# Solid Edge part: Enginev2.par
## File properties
Author: m_hel
Template: iso metric part.par
Last saved by: m_hel
Revision: 22
Application: Solid Edge
Density: 7,750 g/cm^3
Accuracy: 0,990
Username: m_hel
Material: Stainless steel
Face Style: Steel
Fill Style: ANSI32(Steel)
Virtual Style: Stainless steel
Grouping: Metals\Steel
LibraryName: Materials
Coef. of Thermal Exp: 1.6e-05
Thermal Conductivity: 17.0
Specific Heat: 502.0
Modulus of Elasticity: 193053196000.0
Poisson's Ratio: 0.29
Yield Stress: 310264065.0
Ultimate Stress: 641212401.0
Elongation: 0.0
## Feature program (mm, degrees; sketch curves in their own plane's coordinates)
sketch for "unnamed Protrusion 1" plane through (0, 0, 0) normal (0, 0, 1) x-axis (1, 0, 0)
  line (-200, -300) -> (200, -300)
  line (200, -300) -> (200, 300)
  line (200, 300) -> (-200, 300)
  line (-200, 300) -> (-200, -300)
extrude "unnamed Protrusion 1" add finite 100 along +normal
sketch for "ExtrudedProtrusion_2" plane through (0, 0, 0) normal (0, 0, -1) x-axis (0, -1, 0)
  line (-130.9637, 125) -> (-130.9637, -125)
  line (-130.9637, -125) -> (269.0363, -125)
  line (269.0363, -125) -> (269.0363, 125)
  line (269.0363, 125) -> (-130.9637, 125)
extrude "ExtrudedProtrusion_2" add finite 700 along +normal
draft "Draft_1"  Angles1 = 7 deg
sketch for "ExtrudedProtrusion_3" plane through (0, -25.292, -700) normal (0, 0, -1) x-axis (0, -1, 0)
  line (157.7951, 39.0508) -> (-156.2557, 39.0508)
  line (-156.2557, 39.0508) -> (-156.2557, -39.0508)
  line (-156.2557, -39.0508) -> (157.7951, -39.0508)
  line (157.7951, -39.0508) -> (157.7951, 39.0508)
extrude "ExtrudedProtrusion_3" add finite 200 along +normal
sketch for "ExtrudedProtrusion_4" plane through (0, -183.0871, -1100) normal (0, -1, 0) x-axis (1, 0, 0)
  line (39.0508, 400) -> (-39.0508, 400)
  line (-39.0508, 200) -> (-39.0508, 400)
  line (39.0508, 200) -> (-39.0508, 200)
  line (39.0508, 200) -> (39.0508, 400)
extrude "ExtrudedProtrusion_4" add finite 200 along +normal
sketch for "ExtrudedProtrusion_5" plane through (0, -125.292, -900) normal (0, 0, -1) x-axis (0, -1, 0)
  line (-226.2557, -5) -> (-226.2557, 5)
  arc centre (-206.2557, 5) radius 20 from (-226.2557, 5) to (-206.2557, 25) cw
  line (-206.2557, 25) -> (-76.2557, 13.6265)
  line (-76.2557, 13.6265) -> (-76.2557, -13.6265)
  line (-206.2557, -25) -> (-76.2557, -13.6265)
  arc centre (-206.2557, -5) radius 20 from (-226.2557, -5) to (-206.2557, -25) ccw
  dimension (linear) = 76.2557
extrude "ExtrudedProtrusion_5" add finite 450 along +normal
sketch for "ExtrudedProtrusion_6" plane through (0, -49.0363, -1350) normal (0, -1, 0) x-axis (0, 0, 1)
  circle centre (150, 0) radius 60
extrude "ExtrudedProtrusion_6" add finite 105.677 along +normal  FiniteDepth2 = 202.4091 mm
sketch for "ExtrudedProtrusion_7" plane through (0, -154.7133, -1400) normal (0, -1, 0) x-axis (1, 0, 0)
  circle centre (0, 200) radius 15
extrude "ExtrudedProtrusion_7" add finite 80 along +normal
fillet "Round_1" radius 40
sketch for "ExtrudedCutout_1" plane through (0, -281.5477, -700) normal (0, 0, 1) x-axis (0, -1, 0)
  line (-98.4605, -39.0508) -> (101.5395, -14.4939)
  line (101.5395, -14.4939) -> (101.5395, 14.4939)
  line (101.5395, 14.4939) -> (-98.4605, 39.0508)
extrude "ExtrudedCutout_1" cut finite 841.935 along -normal
fillet "Round_2" radius 36
sketch for "ExtrudedProtrusion_8" plane through (0, 0, 100) normal (0, 0, 1) x-axis (0, -1, 0)
  line (-280, 180) -> (-280, -180)
  line (-280, -180) -> (280, -180)
  line (280, -180) -> (280, 180)
  line (280, 180) -> (-280, 180)
extrude "ExtrudedProtrusion_8" add finite 446.6549 along +normal
replace surface "unnamed ReplaceSurface 1"
fillet "Round_3" radius 50
fillet "Round_4" radius 50
fillet "Round_5" radius 32.5
fillet "Round_6" radius 14.625
sketch for "ExtrudedProtrusion_9" plane through (0, 0, 0) normal (0, -1, 0) x-axis (1, 0, 0)
  line (-75, -122.6381) -> (75, -122.6381)
  line (75, -122.6381) -> (75, -92.6381)
  line (75, -92.6381) -> (-75, -92.6381)
  line (-75, -92.6381) -> (-75, -122.6381)
extrude "ExtrudedProtrusion_9" add finite 200 along -normal
sketch for "ExtrudedProtrusion_10" plane through (0, 193.9697, -122.6381) normal (0, 0, -1) x-axis (0, 1, 0)
  circle centre (6.0303, 0) radius 50
extrude "ExtrudedProtrusion_10" add finite 30 along -normal
sketch for "ExtrudedProtrusion_11" plane through (0, 0, 0) normal (1, 0, 0) x-axis (0, 1, 0)
  line (130.9637, -50) -> (160.9637, -72.6381)
  line (160.9637, -72.6381) -> (160.9637, -92.6381)
  line (160.9637, -92.6381) -> (130.9637, -92.6381)
  line (130.9637, -92.6381) -> (130.9637, -50)
  dimension (linear) = 160.9637
extrude "ExtrudedProtrusion_11" add finite 30 symmetric
fillet "Round_7" radius 10
chamfer "Chamfer_1" setback 10
mirror "unnamed Mirror 1" of "ExtrudedProtrusion_11", "ExtrudedProtrusion_10", "Round_7", "ExtrudedProtrusion_9" about plane through (0, 190.4818, -152.6381) normal (0, 0, -1)
extrude "unnamed Protrusion 2" add finite 200
extrude "unnamed Protrusion 3" add finite 30
extrude "unnamed Protrusion 4" add finite 30 symmetric
fillet "unnamed Round 1"
sketch for "unnamed Cutout 1" plane through (0, 218.9697, -92.6381) normal (0, 0, 1) x-axis (-1, 0, 0)
  circle centre (0, 18.9697) radius 25
extrude "unnamed Cutout 1" cut through along -normal
rib "unnamed Rib 1"
chamfer "Chamfer_3" setback 5
lofted protrusion "LoftedProtrusion_1"  EndTangentMagnitude1 = 1
sketch for "ExtrudedCutout_4" plane through (133.75, 340, 66.25) normal (0, 1, 0) x-axis (-1, 0, 0)
  circle centre (0, 0) radius 25
extrude "ExtrudedCutout_4" cut finite 50 along -normal
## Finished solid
Body 1: sheet body, 1 face, 4 edges, 4 vertices.
  Faces by surface: spline 1
  Edges by curve: circle 2, spline 2
Body 2: solid body, 162 faces, 387 edges, 228 vertices.
  Faces by surface: plane 66, cylinder 58, blend 18, sphere 8, spline 5, cone 4, torus 3
  Edges by curve: line 194, circle 106, intersection 45, ellipse 38, spline 4
Bounding box of the edges (mm; curved faces can reach further): 723.467 x 775.717 x 1838.647, from (-361.7335, -417.9835, -1350) to (361.7335, 357.7337, 488.6472).
Cylindrical faces by radius (mm): R10 x16, R14.625 x2, R15 x1, R20 x4, R25 x3, R32.5 x14, R36 x6, R50 x10, R60 x1, R125.7616 x1
Conical faces (half-angle, radius in mm at the cone's reference point): 45 deg R26 x2, 45 deg R125.7616 x1, 45 deg R130.7616 x1
Toroidal faces (ring radius, tube radius in mm): R20 r40 x1, R40 r10 x2
Spherical faces by radius (mm): R32.5 x4, R50 x4
Planar faces by outward normal: +x 8, +y 17, +z 4, -x 8, -y 6, -z 7, oblique 16
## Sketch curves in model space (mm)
circle centre (133.75, 340, 66.25) radius 33.75
line (167.5, 300, 32.5) -> (167.5, 300, 100)
line (167.5, 300, 100) -> (100, 300, 100)
line (100, 300, 100) -> (100, 300, 32.5)
line (100, 300, 32.5) -> (167.5, 300, 32.5)
arc centre (0, 0, -166.6274) radius 655.2478 from (0, 0, 488.6204) through (188.8848, 0, 460.8056) to (361.7335, 0, 379.7228)
arc centre (0, 0, -166.6274) radius 655.2478 from (0, 0, 488.6204) through (-188.8848, 0, 460.8056) to (-361.7335, 0, 379.7228)
spline (0, 357.7337, 404.8039) -> (0, 3.7266, 488.327) -> (0, -417.9835, 466.9366)
line (-180, -280, 100) -> (180, -280, 100)
line (180, -280, 100) -> (180, 280, 100)
line (180, 280, 100) -> (-180, 280, 100)
line (-180, 280, 100) -> (-180, -280, 100)
line (125, -269.0363, 0) -> (-125, -269.0363, 0)
line (-125, -269.0363, 0) -> (-125, 130.9637, 0)
line (-125, 130.9637, 0) -> (125, 130.9637, 0)
line (125, 130.9637, 0) -> (125, -269.0363, 0)
line (200, -300, 0) -> (200, 300, 0)
line (200, 300, 0) -> (-200, 300, 0)
line (-200, 300, 0) -> (-200, -300, 0)
line (-200, -300, 0) -> (200, -300, 0)
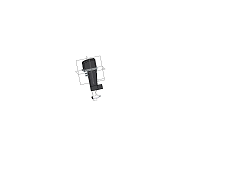
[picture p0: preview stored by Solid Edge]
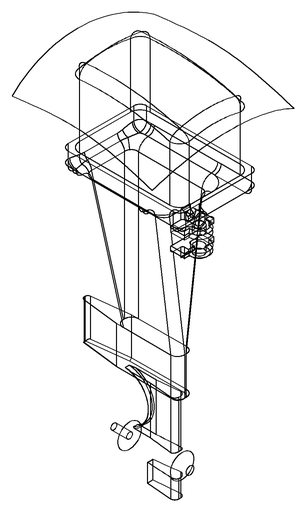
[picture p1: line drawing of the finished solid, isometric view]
